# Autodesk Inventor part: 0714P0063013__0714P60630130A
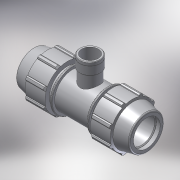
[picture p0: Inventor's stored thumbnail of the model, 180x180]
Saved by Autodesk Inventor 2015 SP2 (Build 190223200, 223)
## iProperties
Created: 2017-02
Part Number: 0714P0063013__0714P60630130A
Material: PVC-Piping
Description: PLASSON TEE FEMALE ADAPTOR WITHOUT STOP 63-1.1/4"
Document SubType Name: Modeling
Designer: KIM
Mass: 92.6774 g
Surface Area: 199.44 cm^2
Volume: 66.1981 cm^3
Density: 1.4 g/cm^3
Appearance: Smooth - White
Author: KIM
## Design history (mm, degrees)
derived "0714P0.ipt"
feature "Solid1::0714P0.ipt"
feature "Solid2::0714P0.ipt"
tag "TaggingFeature1"
body "Solid1"
other parameters: "d2" = 63, "d4" = 11.16667, "d5" = 32.16, "d7" = 113, "d11" = 4.46667, "d13" = 120 deg, "d14" = 81.9, "d15" = 12 deg, "d16" = 98.31, "d18" = 3.15, "d19" = 35 deg, "d20" = 17.5 deg, "d21" = 105.09, "d23" = 0, "d25" = 360 deg, "d27" = 2.26, "d33" = 1.26, "d42" = 48.24, "d43" = 3.39, "d46" = 1.89, "d68" = 8.04, "d72" = 95, "d76" = 38.952, "d80" = 1.16856, "d91" = 84.75, "d93" = 113, "d95" = 56.7, "d112" = 27, "d115" = 48.69, "d116" = 135 deg, "d117" = 44.7948, "d118" = 268, "d119" = 56.7, "d121" = 0, "d122" = 34.02, "d124" = 0, "d128" = 0, "d129" = 6.3, "d130" = 8.1, "d131" = 0.3, "d132" = 0.3, "d133" = 48.69, "d_" = 63, "E_" = 113, "A_" = 95, "l_" = 113, "l_2" = 27, "Rp_" = 38.952, "H_" = 268
